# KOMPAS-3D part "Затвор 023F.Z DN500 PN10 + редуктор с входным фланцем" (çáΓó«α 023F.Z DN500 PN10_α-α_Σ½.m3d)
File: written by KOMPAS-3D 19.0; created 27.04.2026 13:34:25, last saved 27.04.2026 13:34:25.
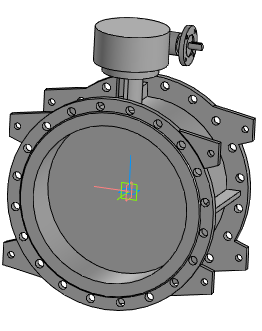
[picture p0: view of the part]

Document properties: Полное имя файла: ..\..\Затвор 023F.Z DN200-DN1600_редуктор с входным фланцем\Затвор 023F.Z DN500 PN10 + редуктор с входным фланцем.a3d

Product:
- Part/product: Затвор 023F.Z DN500 PN10 + редуктор с входным фланцем
    Масса: 257.473

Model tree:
1. Операция без истории:1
